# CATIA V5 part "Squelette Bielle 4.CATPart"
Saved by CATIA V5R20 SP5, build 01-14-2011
Part number: Squelette Bielle 4
Bounding box of the stored display mesh (mm): x -200 to 0, y -250 to -250, z -10 to 50
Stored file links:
  U:\CFAO\Thinkmotion\Squelette Bielle 4.CATPart
  U:\CFAO\Thinkmotion\Bras Articule.CATProduct
  U:\CFAO\Thinkmotion\Squelette general.CATPart
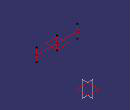
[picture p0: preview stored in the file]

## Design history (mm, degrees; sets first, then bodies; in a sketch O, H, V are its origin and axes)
Set1
  Line1: type PtPt, FirstPoint Point1, SecondPoint Point2
  Line2: type PtPt, FirstPoint Point3, SecondPoint Point2
  Line3: type Normal, RefPoint Point3, RefSkin Plane2, Start -30, End 30
  Line4: type Normal, RefPoint Point2, RefSkin Plane2, Start -30, End 30
  Line5: type Normal, RefPoint Point1, RefSkin Plane2, Start -30, End 30
  Plane1: type OffsetPt, RefPlane xy-plane, RefPoint Point2
Set2
  Point1 to Point3: linked copy from another document
  Plane2: linked copy from another document
Body1 (main body)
